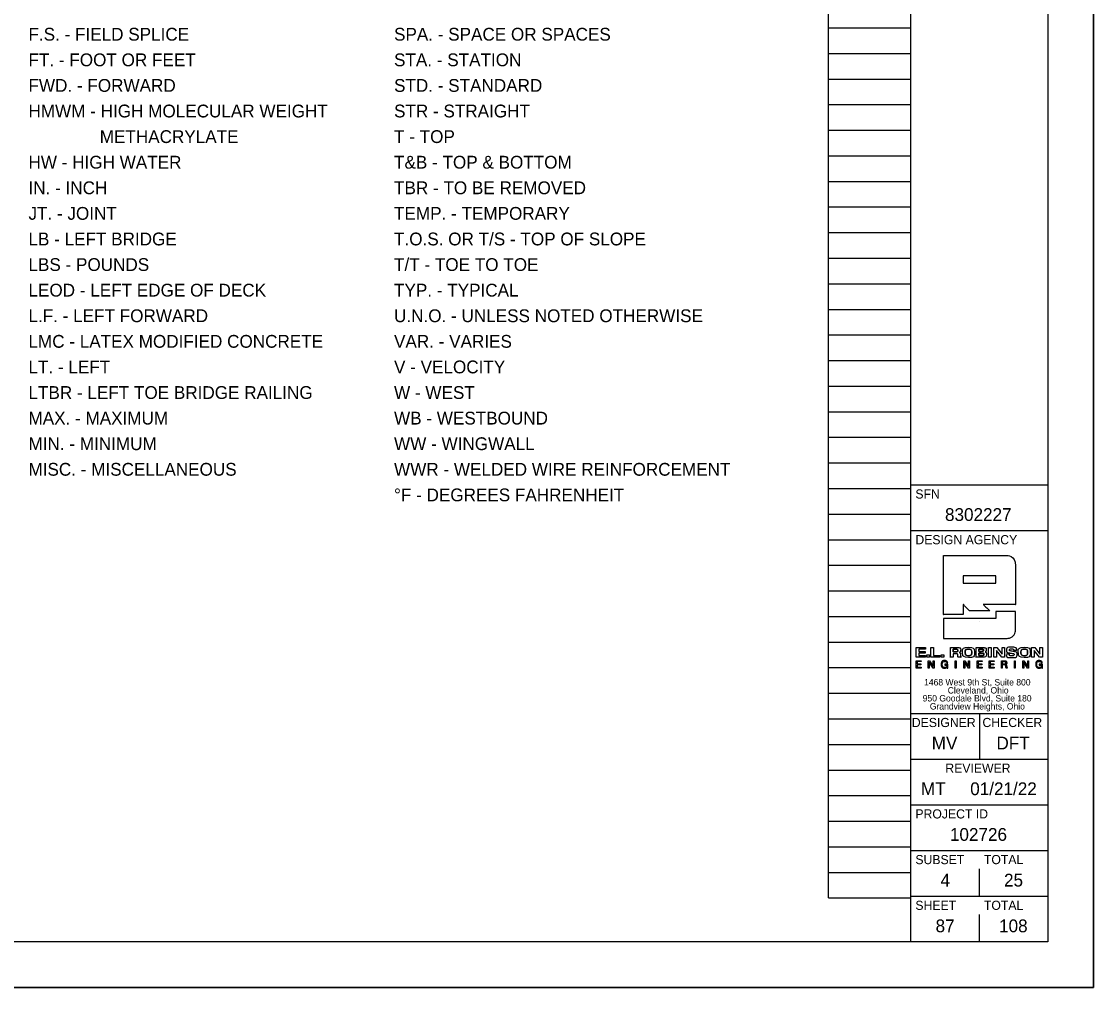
# Model space of a CAD drawing. Extents: x 0 to 34, y 0 to 22.
# Drawn here: x 22.27 to 34, y 0 to 10.57 of the extents above; entities that cross this region are included whole.
import ezdxf

# ---------------------------------------------------------------- set-up
doc = ezdxf.new("R2010")
doc.units = 0
for name, color, linetype in [('BR_P_Gen_Text', 7, 'Continuous'), ('SC_Scratch1', 7, 'Continuous'), ('SH_Border', 7, 'Continuous'), ('SH_Cut_Line', 7, 'Continuous'), ('SH_Data', 7, 'Continuous')]:
    doc.layers.add(name, color=color, linetype=linetype)

msp = doc.modelspace()

# ---------------------------------------------------------------- linework, layer by layer
at = {"layer": 'SC_Scratch1'}
for p, q in [((31.1, 0.98), (31.1, 21.14)), ((32, 0.98), (32, 21.14)), ((31.1, 10.5), (32, 10.5)), ((31.1, 10.22), (32, 10.22)), ((31.1, 9.94), (32, 9.94)), ((31.1, 9.66), (32, 9.66)), ((31.1, 9.38), (32, 9.38)), ((31.1, 9.1), (32, 9.1)), ((31.1, 8.82), (32, 8.82)), ((31.1, 8.54), (32, 8.54)), ((31.1, 8.26), (32, 8.26)), ((31.1, 7.98), (32, 7.98)), ((31.1, 7.7), (32, 7.7)), ((31.1, 7.42), (32, 7.42)), ((31.1, 7.14), (32, 7.14)), ((31.1, 6.86), (32, 6.86)), ((31.1, 6.58), (32, 6.58)), ((31.1, 6.3), (32, 6.3)), ((31.1, 6.02), (32, 6.02)), ((31.1, 5.74), (32, 5.74)), ((31.1, 5.46), (32, 5.46)), ((31.1, 5.18), (32, 5.18)), ((31.1, 4.9), (32, 4.9)), ((31.1, 4.62), (32, 4.62)), ((31.1, 4.34), (32, 4.34)), ((31.1, 4.06), (32, 4.06)), ((31.1, 3.78), (32, 3.78)), ((31.1, 3.5), (32, 3.5)), ((31.1, 3.22), (32, 3.22)), ((31.1, 2.94), (32, 2.94)), ((31.1, 2.66), (32, 2.66)), ((31.1, 2.38), (32, 2.38)), ((31.1, 2.1), (32, 2.1)), ((31.1, 1.82), (32, 1.82)), ((31.1, 1.54), (32, 1.54)), ((31.1, 1.26), (32, 1.26)), ((31.1, 0.98), (32, 0.98))]:
    msp.add_line(p, q, dxfattribs=at)
msp.add_lwpolyline([(0, 22), (34, 22), (34, 0), (0, 0)], close=True, dxfattribs=at)
at = {"layer": 'SH_Border'}
for p, q in [((32, 0.5), (32, 21.5)), ((32, 5.5), (33.5, 5.5)), ((32, 5), (33.5, 5)), ((32, 3), (33.5, 3)), ((32.75, 3), (32.75, 2.5)), ((32, 2.5), (33.5, 2.5)), ((32, 2), (33.5, 2)), ((32, 1.5), (33.5, 1.5)), ((32, 1), (33.5, 1))]:
    msp.add_line(p, q, dxfattribs=at)
msp.add_lwpolyline([(1.5, 21.5), (33.5, 21.5), (33.5, 0.5), (1.5, 0.5)], close=True, dxfattribs=at)
at = {"layer": 'SH_Cut_Line'}
msp.add_lwpolyline([(0, 0), (34, 0), (34, 22), (0, 22)], close=True, dxfattribs=at)
at = {"layer": 'SH_Data'}
for p, q in [((32.929, 4.503), (32.574, 4.503)), ((32.574, 4.503), (32.574, 4.425)), ((32.929, 4.425), (32.929, 4.503)), ((32.574, 4.425), (32.929, 4.425)), ((32.75, 4), (32.75, 4)), ((32.463, 3.701), (32.463, 3.673)), ((32.743, 3.702), (32.743, 3.678)), ((32.743, 3.659), (32.743, 3.633)), ((33.001, 3.566), (33.001, 3.539)), ((33.001, 3.539), (33.023, 3.539)), ((32.75, 1), (32.75, 1.3)), ((32.75, 0.5), (32.75, 0.8)), ((32.375, 0.675), (32.375, 0.675))]:
    msp.add_line(p, q, dxfattribs=at)
for points in [[(32.06, 3.721), (32.161, 3.721), (32.161, 3.701), (32.089, 3.701), (32.089, 3.678), (32.158, 3.678), (32.158, 3.658), (32.089, 3.658), (32.089, 3.633), (32.162, 3.633), (32.162, 3.613), (32.06, 3.613), (32.06, 3.721)], [(32.175, 3.639), (32.205, 3.639), (32.205, 3.613), (32.175, 3.613), (32.175, 3.639)], [(32.22, 3.721), (32.249, 3.721), (32.249, 3.634), (32.316, 3.634), (32.316, 3.613), (32.22, 3.613), (32.22, 3.721)], [(32.331, 3.639), (32.361, 3.639), (32.361, 3.613), (32.331, 3.613), (32.331, 3.639)], [(32.851, 3.721), (32.881, 3.721), (32.881, 3.613), (32.851, 3.613), (32.851, 3.721)], [(32.999, 3.721), (33.027, 3.721), (33.027, 3.613), (32.995, 3.613), (32.936, 3.689), (32.936, 3.689), (32.936, 3.613), (32.907, 3.613), (32.907, 3.721), (32.941, 3.721), (32.999, 3.646), (32.999, 3.646), (32.999, 3.721)], [(33.413, 3.721), (33.442, 3.721), (33.442, 3.613), (33.41, 3.613), (33.35, 3.689), (33.35, 3.689), (33.35, 3.613), (33.321, 3.613), (33.321, 3.721), (33.356, 3.721), (33.413, 3.646), (33.413, 3.646), (33.413, 3.721)], [(32.059, 3.575), (32.114, 3.575), (32.114, 3.566), (32.07, 3.566), (32.07, 3.541), (32.111, 3.541), (32.111, 3.532), (32.07, 3.532), (32.07, 3.505), (32.114, 3.505), (32.114, 3.496), (32.059, 3.496), (32.059, 3.575)], [(32.191, 3.575), (32.203, 3.575), (32.244, 3.511), (32.244, 3.511), (32.244, 3.575), (32.254, 3.575), (32.254, 3.496), (32.243, 3.496), (32.202, 3.559), (32.201, 3.559), (32.201, 3.496), (32.191, 3.496), (32.191, 3.575)], [(32.487, 3.575), (32.498, 3.575), (32.498, 3.496), (32.487, 3.496), (32.487, 3.575)], [(32.581, 3.575), (32.592, 3.575), (32.633, 3.511), (32.633, 3.511), (32.633, 3.575), (32.643, 3.575), (32.643, 3.496), (32.632, 3.496), (32.591, 3.559), (32.591, 3.559), (32.591, 3.496), (32.581, 3.496), (32.581, 3.575)], [(32.726, 3.575), (32.781, 3.575), (32.781, 3.566), (32.737, 3.566), (32.737, 3.541), (32.778, 3.541), (32.778, 3.532), (32.737, 3.532), (32.737, 3.505), (32.781, 3.505), (32.781, 3.496), (32.726, 3.496), (32.726, 3.575)], [(32.859, 3.575), (32.913, 3.575), (32.913, 3.566), (32.869, 3.566), (32.869, 3.541), (32.91, 3.541), (32.91, 3.532), (32.869, 3.532), (32.869, 3.505), (32.913, 3.505), (32.913, 3.496), (32.859, 3.496), (32.859, 3.575)], [(33.133, 3.575), (33.143, 3.575), (33.143, 3.496), (33.133, 3.496), (33.133, 3.575)], [(33.226, 3.575), (33.237, 3.575), (33.279, 3.511), (33.279, 3.511), (33.279, 3.575), (33.289, 3.575), (33.289, 3.496), (33.277, 3.496), (33.236, 3.559), (33.236, 3.559), (33.236, 3.496), (33.226, 3.496), (33.226, 3.575)]]:
    msp.add_lwpolyline(points, dxfattribs=at)
for points, degree in [([(32.356, 4.083), (32.356, 4.086), (32.356, 4.724), (32.356, 4.727)], 2), ([(32.356, 4.727), (32.36, 4.727), (33.03, 4.727), (33.034, 4.727), (33.096, 4.727), (33.147, 4.677), (33.147, 4.614)], 3), ([(33.147, 4.614), (33.147, 4.612), (33.147, 4.194), (33.147, 4.192)], 2), ([(32.929, 4.115), (32.929, 4.115), (33.147, 4.115), (33.147, 4.115), (33.147, 4.115), (33.147, 3.933), (33.147, 3.933), (33.147, 3.87), (33.096, 3.82), (33.034, 3.82), (33.034, 3.82), (32.356, 3.82), (32.356, 3.82), (32.356, 3.82), (32.356, 4.037), (32.356, 4.037), (32.356, 4.037), (32.929, 4.037), (32.929, 4.037), (32.929, 4.037), (32.929, 4.115), (32.929, 4.115)], 3), ([(32.645, 4.121), (32.645, 4.121), (32.574, 4.191), (32.574, 4.192)], 2), ([(32.574, 4.192), (32.574, 4.191), (32.574, 4.083), (32.574, 4.083)], 2), ([(32.866, 4.121), (32.865, 4.121), (32.646, 4.121), (32.645, 4.121)], 2), ([(33.147, 4.192), (33.145, 4.192), (32.795, 4.192), (32.793, 4.192)], 2), ([(32.793, 4.192), (32.793, 4.191), (32.866, 4.121), (32.866, 4.121)], 2), ([(32.574, 4.083), (32.573, 4.083), (32.357, 4.083), (32.356, 4.083)], 2), ([(32.433, 3.613), (32.433, 3.613), (32.433, 3.721), (32.433, 3.721)], 2), ([(32.433, 3.721), (32.433, 3.721), (32.512, 3.721), (32.512, 3.721), (32.542, 3.721), (32.545, 3.703), (32.546, 3.692)], 3), ([(32.499, 3.653), (32.499, 3.653), (32.463, 3.653), (32.463, 3.653)], 2), ([(32.463, 3.673), (32.463, 3.673), (32.502, 3.673), (32.502, 3.673), (32.508, 3.673), (32.516, 3.677), (32.516, 3.687), (32.516, 3.698), (32.507, 3.701), (32.5, 3.701), (32.5, 3.701), (32.463, 3.701), (32.463, 3.701), (32.463, 3.701), (32.463, 3.673), (32.463, 3.673)], 3), ([(32.463, 3.673), (32.476, 3.673), (32.489, 3.673), (32.508, 3.673), (32.516, 3.677), (32.516, 3.698), (32.507, 3.701), (32.488, 3.701), (32.475, 3.701), (32.463, 3.701)], 3), ([(32.463, 3.653), (32.463, 3.652), (32.463, 3.613), (32.463, 3.613)], 2), ([(32.518, 3.613), (32.516, 3.618), (32.516, 3.622), (32.516, 3.634), (32.515, 3.649), (32.508, 3.65), (32.499, 3.653)], 3), ([(32.546, 3.692), (32.544, 3.679), (32.542, 3.67), (32.53, 3.666)], 2), ([(32.53, 3.666), (32.53, 3.666), (32.53, 3.665), (32.53, 3.665)], 2), ([(32.53, 3.665), (32.543, 3.663), (32.544, 3.647), (32.544, 3.636)], 2), ([(32.631, 3.61), (32.573, 3.61), (32.567, 3.645), (32.565, 3.667), (32.564, 3.69), (32.573, 3.724), (32.631, 3.724)], 3), ([(32.631, 3.63), (32.658, 3.63), (32.667, 3.65), (32.667, 3.667), (32.667, 3.684), (32.658, 3.704), (32.631, 3.704), (32.604, 3.704), (32.595, 3.684), (32.595, 3.667), (32.595, 3.65), (32.604, 3.63), (32.631, 3.63)], 3), ([(32.631, 3.704), (32.604, 3.704), (32.595, 3.684), (32.595, 3.667), (32.595, 3.65), (32.604, 3.63), (32.631, 3.63)], 3), ([(32.631, 3.724), (32.69, 3.724), (32.695, 3.689), (32.697, 3.667), (32.699, 3.644), (32.69, 3.61), (32.631, 3.61)], 3), ([(32.631, 3.63), (32.658, 3.63), (32.667, 3.65), (32.667, 3.667), (32.667, 3.684), (32.658, 3.704), (32.631, 3.704)], 3), ([(32.714, 3.613), (32.714, 3.613), (32.714, 3.721), (32.714, 3.721)], 2), ([(32.714, 3.721), (32.714, 3.721), (32.795, 3.721), (32.795, 3.721)], 2), ([(32.829, 3.645), (32.827, 3.632), (32.824, 3.613), (32.791, 3.613), (32.791, 3.613), (32.714, 3.613), (32.714, 3.613)], 3), ([(32.743, 3.678), (32.743, 3.678), (32.784, 3.678), (32.784, 3.678), (32.791, 3.678), (32.796, 3.682), (32.796, 3.69), (32.796, 3.697), (32.793, 3.702), (32.78, 3.702), (32.78, 3.702), (32.743, 3.702), (32.743, 3.702), (32.743, 3.702), (32.743, 3.678), (32.743, 3.678)], 3), ([(32.743, 3.678), (32.757, 3.678), (32.771, 3.678), (32.791, 3.681), (32.791, 3.683), (32.792, 3.697), (32.793, 3.702), (32.768, 3.702), (32.756, 3.702), (32.743, 3.702)], 3), ([(32.743, 3.633), (32.743, 3.633), (32.787, 3.633), (32.787, 3.633), (32.796, 3.633), (32.8, 3.639), (32.8, 3.646), (32.8, 3.655), (32.794, 3.659), (32.784, 3.659), (32.784, 3.659), (32.743, 3.659), (32.743, 3.659), (32.743, 3.659), (32.743, 3.633), (32.743, 3.633)], 3), ([(32.743, 3.633), (32.758, 3.633), (32.772, 3.633), (32.796, 3.633), (32.8, 3.639), (32.8, 3.655), (32.794, 3.659), (32.77, 3.659), (32.757, 3.659), (32.743, 3.659)], 3), ([(32.795, 3.721), (32.81, 3.718), (32.826, 3.714), (32.826, 3.694)], 2), ([(32.826, 3.694), (32.824, 3.686), (32.822, 3.675), (32.812, 3.672)], 2), ([(32.812, 3.672), (32.812, 3.672), (32.812, 3.672), (32.812, 3.672)], 2), ([(32.812, 3.672), (32.824, 3.67), (32.827, 3.656), (32.829, 3.645)], 2), ([(33.126, 3.69), (33.124, 3.704), (33.111, 3.706), (33.099, 3.706), (33.087, 3.706), (33.079, 3.7), (33.079, 3.693), (33.079, 3.687), (33.084, 3.684), (33.091, 3.683), (33.091, 3.683), (33.128, 3.677), (33.128, 3.677), (33.148, 3.673), (33.163, 3.666), (33.163, 3.646), (33.163, 3.626), (33.149, 3.61), (33.107, 3.61), (33.08, 3.61), (33.046, 3.613), (33.045, 3.647), (33.045, 3.647), (33.079, 3.647), (33.079, 3.647), (33.079, 3.632), (33.094, 3.629), (33.107, 3.629), (33.121, 3.629), (33.13, 3.634), (33.13, 3.643), (33.13, 3.651), (33.123, 3.654), (33.112, 3.655), (33.112, 3.655), (33.085, 3.66), (33.085, 3.66), (33.066, 3.662), (33.047, 3.668), (33.047, 3.69), (33.047, 3.715), (33.067, 3.724), (33.101, 3.724), (33.124, 3.724), (33.157, 3.721), (33.159, 3.69), (33.159, 3.69), (33.126, 3.69), (33.126, 3.69)], 3), ([(33.242, 3.61), (33.183, 3.61), (33.178, 3.645), (33.176, 3.667), (33.174, 3.69), (33.183, 3.724), (33.242, 3.724)], 3), ([(33.242, 3.63), (33.269, 3.63), (33.278, 3.65), (33.278, 3.667), (33.278, 3.684), (33.269, 3.704), (33.242, 3.704), (33.215, 3.704), (33.205, 3.684), (33.205, 3.667), (33.205, 3.65), (33.215, 3.63), (33.242, 3.63)], 3), ([(33.242, 3.704), (33.215, 3.704), (33.205, 3.684), (33.205, 3.667), (33.205, 3.65), (33.215, 3.63), (33.242, 3.63)], 3), ([(33.242, 3.724), (33.3, 3.724), (33.306, 3.689), (33.308, 3.667), (33.309, 3.644), (33.3, 3.61), (33.242, 3.61)], 3), ([(33.242, 3.63), (33.269, 3.63), (33.278, 3.65), (33.278, 3.667), (33.278, 3.684), (33.269, 3.704), (33.242, 3.704)], 3), ([(32.396, 3.506), (32.39, 3.498), (32.38, 3.494), (32.37, 3.494), (32.347, 3.494), (32.333, 3.514), (32.333, 3.534), (32.333, 3.557), (32.346, 3.577), (32.37, 3.577), (32.388, 3.577), (32.401, 3.569), (32.404, 3.551), (32.404, 3.551), (32.394, 3.551), (32.394, 3.551), (32.392, 3.562), (32.382, 3.568), (32.37, 3.568), (32.351, 3.568), (32.344, 3.551), (32.344, 3.534), (32.344, 3.518), (32.353, 3.503), (32.37, 3.503), (32.387, 3.503), (32.396, 3.515), (32.396, 3.529), (32.396, 3.529), (32.371, 3.529), (32.371, 3.529), (32.371, 3.529), (32.371, 3.538), (32.371, 3.538), (32.371, 3.538), (32.405, 3.538), (32.405, 3.538), (32.405, 3.538), (32.405, 3.496), (32.405, 3.496), (32.405, 3.496), (32.398, 3.496), (32.398, 3.496), (32.398, 3.496), (32.396, 3.506), (32.396, 3.506)], 3), ([(32.463, 3.613), (32.462, 3.613), (32.433, 3.613), (32.433, 3.613)], 2), ([(32.55, 3.613), (32.55, 3.613), (32.518, 3.613), (32.518, 3.613)], 2), ([(32.544, 3.636), (32.544, 3.631), (32.548, 3.619), (32.55, 3.613)], 2), ([(32.991, 3.575), (32.991, 3.575), (33.027, 3.575), (33.028, 3.575), (33.042, 3.575), (33.051, 3.567), (33.051, 3.554)], 3), ([(32.991, 3.496), (32.991, 3.497), (32.991, 3.574), (32.991, 3.575)], 2), ([(33.023, 3.539), (33.033, 3.539), (33.041, 3.541), (33.041, 3.552), (33.041, 3.56), (33.037, 3.566), (33.027, 3.566), (33.027, 3.566), (33.001, 3.566), (33.001, 3.566), (33.001, 3.566), (33.001, 3.539), (33.001, 3.539), (33.001, 3.539), (33.023, 3.539), (33.023, 3.539)], 3), ([(33.023, 3.539), (33.033, 3.539), (33.041, 3.541), (33.041, 3.56), (33.037, 3.566), (33.018, 3.566), (33.01, 3.566), (33.001, 3.566)], 3), ([(33.04, 3.516), (33.038, 3.523), (33.037, 3.53), (33.027, 3.53), (33.027, 3.53), (33.001, 3.53), (33.001, 3.53)], 3), ([(33.001, 3.53), (33.001, 3.53), (33.001, 3.496), (33.001, 3.496)], 2), ([(33.051, 3.554), (33.049, 3.545), (33.047, 3.537), (33.038, 3.534)], 2), ([(33.038, 3.534), (33.038, 3.534), (33.038, 3.534), (33.038, 3.534)], 2), ([(33.038, 3.534), (33.044, 3.529), (33.047, 3.525), (33.048, 3.518)], 2), ([(33.43, 3.506), (33.424, 3.498), (33.414, 3.494), (33.405, 3.494), (33.382, 3.494), (33.368, 3.514), (33.368, 3.534), (33.368, 3.557), (33.38, 3.577), (33.405, 3.577), (33.422, 3.577), (33.436, 3.569), (33.439, 3.551), (33.439, 3.551), (33.429, 3.551), (33.429, 3.551), (33.426, 3.562), (33.417, 3.568), (33.405, 3.568), (33.386, 3.568), (33.378, 3.551), (33.378, 3.534), (33.378, 3.518), (33.388, 3.503), (33.405, 3.503), (33.421, 3.503), (33.431, 3.515), (33.43, 3.529), (33.43, 3.529), (33.405, 3.529), (33.405, 3.529), (33.405, 3.529), (33.405, 3.538), (33.405, 3.538), (33.405, 3.538), (33.44, 3.538), (33.44, 3.538), (33.44, 3.538), (33.44, 3.496), (33.44, 3.496), (33.44, 3.496), (33.433, 3.496), (33.433, 3.496), (33.433, 3.496), (33.43, 3.506), (33.43, 3.506)], 3), ([(33.001, 3.496), (33.001, 3.496), (32.991, 3.496), (32.991, 3.496)], 2), ([(33.043, 3.496), (33.042, 3.5), (33.041, 3.508), (33.04, 3.516)], 2), ([(33.054, 3.496), (33.054, 3.496), (33.043, 3.496), (33.043, 3.496)], 2), ([(33.048, 3.518), (33.049, 3.51), (33.052, 3.502), (33.054, 3.496)], 2)]:
    msp.add_open_spline(points, degree=degree, dxfattribs=at)

# ---------------------------------------------------------------- texts
at = {"layer": 'BR_P_Gen_Text'}
for s, p in [('   F.S. - FIELD SPLICE', (22.187, 10.36)), ('   SPA. - SPACE OR SPACES', (26.188, 10.36)), ('   FT. - FOOT OR FEET', (22.187, 10.08)), ('   STA. - STATION', (26.188, 10.08)), ('   FWD. - FORWARD', (22.187, 9.8)), ('   STD. - STANDARD', (26.188, 9.8)), ('   HMWM - HIGH MOLECULAR WEIGHT', (22.187, 9.52)), ('   STR - STRAIGHT', (26.188, 9.52)), ('                  METHACRYLATE', (22.187, 9.24)), ('   T - TOP', (26.188, 9.24)), ('   HW - HIGH WATER', (22.187, 8.96)), ('   T&B - TOP & BOTTOM', (26.188, 8.96)), ('   IN. - INCH', (22.187, 8.68)), ('   TBR - TO BE REMOVED   ', (26.188, 8.68)), ('   JT. - JOINT', (22.187, 8.4)), ('   TEMP. - TEMPORARY', (26.188, 8.4)), ('   LB - LEFT BRIDGE', (22.187, 8.12)), ('   T.O.S. OR T/S - TOP OF SLOPE', (26.188, 8.12)), ('   LBS - POUNDS', (22.187, 7.84)), ('   T/T - TOE TO TOE      ', (26.188, 7.84)), ('   LEOD - LEFT EDGE OF DECK', (22.187, 7.56)), ('   TYP. - TYPICAL', (26.188, 7.56)), ('   L.F. - LEFT FORWARD', (22.187, 7.28)), ('   U.N.O. - UNLESS NOTED OTHERWISE', (26.188, 7.28)), ('   LMC - LATEX MODIFIED CONCRETE', (22.187, 7)), ('   VAR. - VARIES', (26.188, 7)), ('   LT. - LEFT', (22.187, 6.72)), ('   V - VELOCITY', (26.188, 6.72)), ('   LTBR - LEFT TOE BRIDGE RAILING', (22.187, 6.44)), ('   W - WEST', (26.188, 6.44)), ('   MAX. - MAXIMUM  ', (22.187, 6.16)), ('   WB - WESTBOUND', (26.188, 6.16)), ('   MIN. - MINIMUM', (22.187, 5.88)), ('   WW - WINGWALL', (26.188, 5.88)), ('   MISC. - MISCELLANEOUS', (22.187, 5.6)), ('   WWR - WELDED WIRE REINFORCEMENT', (26.188, 5.6)), ('   °F - DEGREES FAHRENHEIT', (26.188, 5.32))]:
    msp.add_text(s, height=0.14, dxfattribs=at).set_placement(p)
at = {"layer": 'SH_Data'}
for s, height, p in [('SFN', 0.1, (32.05, 5.35)), ('8302227', 0.14, (32.374, 5.105)), ('DESIGN AGENCY', 0.1, (32.05, 4.85)), ('1468 West 9th St, Suite 800', 0.07, (32.145, 3.305)), ('Cleveland, Ohio', 0.07, (32.404, 3.217)), ('950 Goodale Blvd, Suite 180', 0.07, (32.13, 3.13)), ('Grandview Heights, Ohio', 0.07, (32.208, 3.042)), ('DESIGNER', 0.1, (32.011, 2.85)), ('CHECKER', 0.1, (32.784, 2.85)), ('MV', 0.14, (32.229, 2.605)), ('DFT', 0.14, (32.937, 2.605)), ('REVIEWER', 0.1, (32.378, 2.35)), ('MT', 0.14, (32.111, 2.105)), ('01/21/22', 0.14, (32.65, 2.105)), ('PROJECT ID', 0.1, (32.05, 1.85)), ('102726', 0.14, (32.428, 1.605)), ('SUBSET', 0.1, (32.05, 1.35)), ('TOTAL', 0.1, (32.8, 1.35)), ('4', 0.14, (32.325, 1.105)), ('25', 0.14, (33.02, 1.105)), ('SHEET', 0.1, (32.05, 0.85)), ('TOTAL', 0.1, (32.8, 0.85)), ('87', 0.14, (32.271, 0.605)), ('108', 0.14, (32.966, 0.605))]:
    msp.add_text(s, height=height, dxfattribs=at).set_placement(p)

doc.saveas('drawing.dxf')
